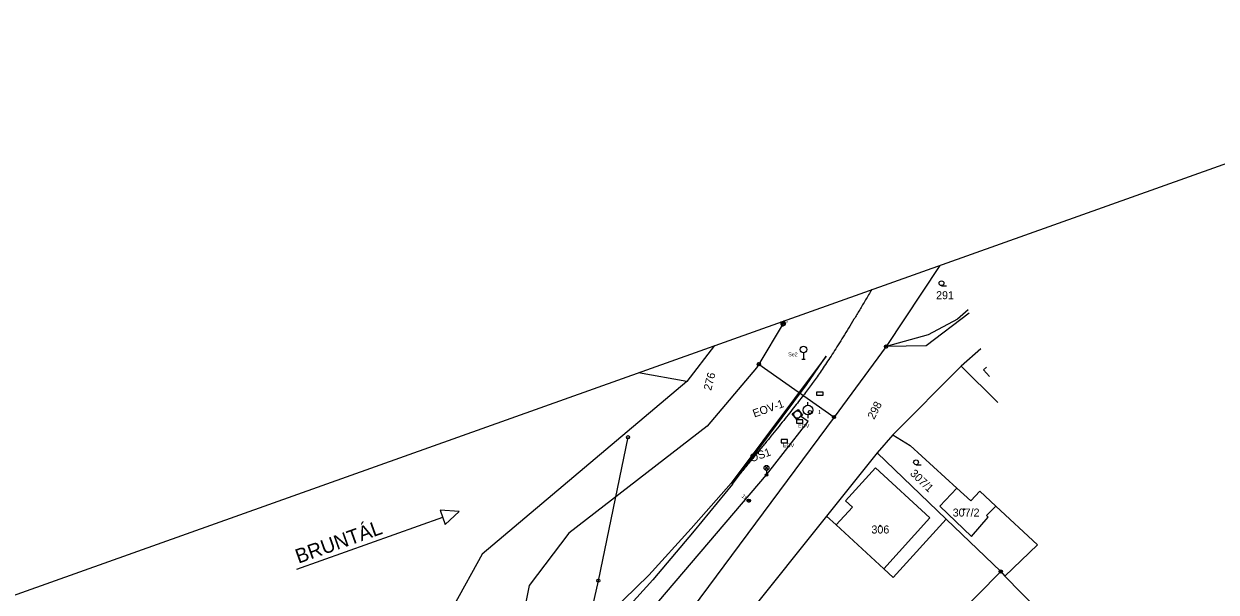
# Model space of a CAD drawing. Extents: x -734423 to 647242, y -1165906 to -111601.
# Drawn here: x -532656.7 to -532470.9, y -1114252 to -1114163.4 of the extents above; entities that cross this region are included whole.
import ezdxf

# ---------------------------------------------------------------- set-up
doc = ezdxf.new("R2010")
doc.units = 0
for name, color, linetype in [('Vrstva 1', 7, 'Continuous'), ('Vrstva 11', 7, 'Continuous'), ('Vrstva 13', 7, 'Continuous'), ('Vrstva 14', 7, 'Continuous'), ('Vrstva 15', 7, 'Continuous'), ('Vrstva 16', 7, 'Continuous'), ('Vrstva 17', 7, 'Continuous'), ('Vrstva 18', 7, 'Continuous'), ('Vrstva 19', 7, 'Continuous'), ('Vrstva 2', 7, 'Continuous'), ('Vrstva 24', 7, 'Continuous'), ('Vrstva 26', 7, 'Continuous'), ('Vrstva 4', 7, 'Continuous'), ('Vrstva 7', 7, 'Continuous'), ('Vrstva 8', 7, 'Continuous')]:
    doc.layers.add(name, color=color, linetype=linetype)

msp = doc.modelspace()

# ---------------------------------------------------------------- linework, layer by layer
at = {"layer": 'Vrstva 1'}
for p, q in [((-532588.86, -1114239.44), (-532591.83, -1114239.27)), ((-532591.83, -1114239.27), (-532591.03, -1114241.51)), ((-532591.03, -1114241.51), (-532588.86, -1114239.44)), ((-532614.17, -1114248.47), (-532591.44, -1114240.36))]:
    msp.add_line(p, q, dxfattribs=at)
at = {"layer": 'Vrstva 13'}
for p, q in [((-532509.35, -1114208.55), (-532516.07, -1114213.62)), ((-532516.07, -1114213.62), (-532522.32, -1114213.73)), ((-532528.66, -1114237.77), (-532523.97, -1114232.66)), ((-532523.97, -1114232.66), (-532515.52, -1114240.46)), ((-532527.58, -1114238.77), (-532528.66, -1114237.77)), ((-532530.12, -1114241.56), (-532527.58, -1114238.77)), ((-532515.52, -1114240.46), (-532522.68, -1114248.4))]:
    msp.add_line(p, q, dxfattribs=at)
at = {"layer": 'Vrstva 14'}
for p, q in [((-532513.96, -1114201.07), (-532522.32, -1114213.73)), ((-532509.53, -1114208.01), (-532511.21, -1114209.45)), ((-532538.38, -1114210.13), (-532542.14, -1114216.46)), ((-532538.21, -1114209.72), (-532538.38, -1114210.13)), ((-532511.21, -1114209.45), (-532515.78, -1114211.89)), ((-532515.78, -1114211.89), (-532522.32, -1114213.73)), ((-532549.07, -1114213.59), (-532553.37, -1114219.18)), ((-532522.32, -1114213.73), (-532530.44, -1114224.72)), ((-532507.57, -1114214.11), (-532510.62, -1114216.81)), ((-532560.9, -1114217.85), (-532560.93, -1114217.82)), ((-532553.37, -1114219.18), (-532560.9, -1114217.85)), ((-532542.5, -1114217.06), (-532550.19, -1114226.17)), ((-532542.14, -1114216.46), (-532542.5, -1114217.06)), ((-532542.14, -1114216.46), (-532530.44, -1114224.72)), ((-532510.62, -1114216.81), (-532521.29, -1114227.49)), ((-532510.62, -1114216.81), (-532504.88, -1114222.48)), ((-532507.12, -1114217.37), (-532506.66, -1114216.95)), ((-532506.2, -1114218.38), (-532507.12, -1114217.37)), ((-532553.37, -1114219.18), (-532585.27, -1114246.09)), ((-532530.44, -1114224.72), (-532572.43, -1114281.44)), ((-532550.19, -1114226.17), (-532571.79, -1114242.85)), ((-532521.29, -1114227.49), (-532523.7, -1114230.3)), ((-532521.29, -1114227.49), (-532518.59, -1114229.18)), ((-532518.59, -1114229.18), (-532511.28, -1114235.8)), ((-532523.7, -1114230.3), (-532531.61, -1114240.18)), ((-532512.98, -1114240.64), (-532523.7, -1114230.3)), ((-532511.28, -1114235.8), (-532513.94, -1114238.65)), ((-532511.28, -1114235.8), (-532509.12, -1114237.78)), ((-532509.12, -1114237.78), (-532507.7, -1114236.29)), ((-532507.7, -1114236.29), (-532505.24, -1114238.64)), ((-532531.61, -1114240.18), (-532544.05, -1114255.71)), ((-532531.61, -1114240.18), (-532530.12, -1114241.56)), ((-532513.94, -1114238.65), (-532509, -1114243.34)), ((-532506.69, -1114240.1), (-532505.24, -1114238.64)), ((-532506.4, -1114240.36), (-532506.69, -1114240.1)), ((-532505.24, -1114238.64), (-532498.72, -1114244.68)), ((-532530.12, -1114241.56), (-532522.68, -1114248.4)), ((-532521.21, -1114249.73), (-532512.98, -1114240.64)), ((-532504.46, -1114248.83), (-532512.98, -1114240.64)), ((-532509, -1114243.34), (-532506.4, -1114240.36)), ((-532571.79, -1114242.85), (-532577.97, -1114250.99)), ((-532498.72, -1114244.68), (-532503.79, -1114249.53)), ((-532585.27, -1114246.09), (-532589.68, -1114254.1)), ((-532522.68, -1114248.4), (-532521.21, -1114249.73)), ((-532520.48, -1114265.02), (-532504.46, -1114248.83)), ((-532504.46, -1114248.83), (-532503.79, -1114249.53)), ((-532503.79, -1114249.53), (-532498.62, -1114254.82)), ((-532577.97, -1114250.99), (-532580.38, -1114262.9))]:
    msp.add_line(p, q, dxfattribs=at)
at = {"layer": 'Vrstva 15'}
for p, q in [((-532531.68, -1114215.22), (-532546.47, -1114235.05)), ((-532535.44, -1114215.69), (-532534.94, -1114215.69)), ((-532535.19, -1114214.69), (-532535.19, -1114215.69)), ((-532534.72, -1114219.68), (-532531.68, -1114215.22)), ((-532546.27, -1114235.22), (-532534.72, -1114219.68)), ((-532534.5, -1114222.89), (-532534.5, -1114222.39)), ((-532534.5, -1114224.39), (-532534.5, -1114224.89)), ((-532541.23, -1114232.9), (-532540.71, -1114232.37)), ((-532541.23, -1114232.37), (-532540.71, -1114232.9)), ((-532540.97, -1114233.01), (-532540.97, -1114233.56)), ((-532546.47, -1114235.05), (-532552.68, -1114242.09)), ((-532546.27, -1114235.22), (-532552.26, -1114242.49)), ((-532559.33, -1114249.4), (-532552.68, -1114242.09)), ((-532552.26, -1114242.49), (-532558.67, -1114250.13)), ((-532565.21, -1114255.16), (-532559.33, -1114249.4)), ((-532558.67, -1114250.13), (-532564.19, -1114256.18))]:
    msp.add_line(p, q, dxfattribs=at)
for points in [[(-532533.15, -1114221.33), (-532532.15, -1114221.33), (-532532.15, -1114220.83), (-532533.15, -1114220.83)], [(-532536.3, -1114225.68), (-532535.3, -1114225.68), (-532535.3, -1114225.18), (-532536.3, -1114225.18)], [(-532538.7, -1114228.73), (-532537.7, -1114228.73), (-532537.7, -1114228.23), (-532538.7, -1114228.23)]]:
    msp.add_lwpolyline(points, close=True, dxfattribs=at)
for centre, radius in [((-532535.19, -1114214.19), 0.5), ((-532534.5, -1114223.64), 0.75), ((-532534.2, -1114223.95), 0.25), ((-532562.56, -1114227.88), 0.25), ((-532540.97, -1114232.64), 0.375), ((-532540.97, -1114233.76), 0.2), ((-532567.18, -1114250.25), 0.25)]:
    msp.add_circle(centre, radius, dxfattribs=at)
msp.add_open_spline([(-532524.57, -1114204.85), (-532530.44, -1114214.87), (-532537.33, -1114224.26), (-532544.98, -1114233.43)], degree=2, dxfattribs=at)
at = {"layer": 'Vrstva 16'}
for p, q in [((-532522.32, -1114213.73), (-532522.32, -1114213.73)), ((-532542.14, -1114216.46), (-532542.14, -1114216.46)), ((-532530.44, -1114224.72), (-532530.44, -1114224.72)), ((-532504.46, -1114248.83), (-532504.46, -1114248.83))]:
    msp.add_line(p, q, dxfattribs=at)
for centre, radius in [((-532522.32, -1114213.73), 0.258), ((-532522.32, -1114213.73), 0.25), ((-532522.32, -1114213.73), 0.05), ((-532522.32, -1114213.73), 0.05), ((-532542.14, -1114216.46), 0.258), ((-532542.14, -1114216.46), 0.25), ((-532542.14, -1114216.46), 0.05), ((-532542.14, -1114216.46), 0.05), ((-532530.44, -1114224.72), 0.258), ((-532530.44, -1114224.72), 0.25), ((-532530.44, -1114224.72), 0.05), ((-532530.44, -1114224.72), 0.05), ((-532504.46, -1114248.83), 0.258), ((-532504.46, -1114248.83), 0.25), ((-532504.46, -1114248.83), 0.05), ((-532504.46, -1114248.83), 0.05)]:
    msp.add_circle(centre, radius, dxfattribs=at)
at = {"layer": 'Vrstva 17'}
msp.add_circle((-532538.38, -1114210.12), 0.0164, dxfattribs=at)
msp.add_arc((-532538.38, -1114210.12), 0.375, 140.0548, 79.193, dxfattribs=at)
at = {"layer": 'Vrstva 18'}
for radius in [0.188, 0.00025]:
    msp.add_circle((-532538.38, -1114210.12), radius, dxfattribs=at)
at = {"layer": 'Vrstva 19'}
for p, q in [((-532513.68, -1114204.24), (-532512.88, -1114204.24)), ((-532517.65, -1114232.16), (-532516.85, -1114232.16))]:
    msp.add_line(p, q, dxfattribs=at)
for centre, radius in [((-532513.68, -1114203.86), 0.375), ((-532517.65, -1114231.78), 0.375), ((-532510.17, -1114239.11), 0.0875), ((-532523.25, -1114241.69), 0.0875)]:
    msp.add_circle(centre, radius, dxfattribs=at)
at = {"layer": 'Vrstva 2'}
msp.add_lwpolyline([(-532846.62, -1114416.18), (-532848.11, -1114412.13), (-532808.84, -1114398.2), (-532780.05, -1114388.6), (-532754.69, -1114379.36), (-532726.64, -1114369.2), (-532698.29, -1114356.28), (-532677.56, -1114346.43), (-532659.12, -1114337.79), (-532635.25, -1114325.58), (-532614.01, -1114308.56), (-532586.09, -1114284.59), (-532565.53, -1114262.57), (-532540.97, -1114233.76), (-532534.45, -1114225.44), (-532535.66, -1114224.61)], dxfattribs=at)
at = {"layer": 'Vrstva 24'}
msp.add_lwpolyline([(-532562.56, -1114227.88), (-532567.18, -1114250.25), (-532573.56, -1114278.28), (-532581.66, -1114307.38), (-532563.97, -1114281.96)], dxfattribs=at)
at = {"layer": 'Vrstva 26'}
for radius in [0.25, 0.05]:
    msp.add_circle((-532543.71, -1114237.76), radius, dxfattribs=at)
at = {"layer": 'Vrstva 4'}
msp.add_line((-533100.62, -1114410.25), (-532408.31, -1114163.4), dxfattribs=at)
at = {"layer": 'Vrstva 7'}
for p, q in [((-532536.94, -1114224.23), (-532536.05, -1114223.53)), ((-532536.05, -1114223.53), (-532535.35, -1114224.42)), ((-532536.24, -1114225.12), (-532536.94, -1114224.23)), ((-532535.35, -1114224.42), (-532536.24, -1114225.12))]:
    msp.add_line(p, q, dxfattribs=at)
msp.add_circle((-532536.15, -1114224.32), 0.563, dxfattribs=at)

# ---------------------------------------------------------------- texts
at = {"layer": 'Vrstva 1'}
msp.add_text('BRUNTÁL', height=2.257, rotation=19.6237, dxfattribs=at).set_placement((-532613.92, -1114247.61))
at = {"layer": 'Vrstva 11'}
for s, rotation, p in [('291', 359.9996, (-532514.53, -1114206.35)), ('276', 75.5726, (-532549.59, -1114220.66)), ('298', 63.0248, (-532524.19, -1114225.19)), ('307/1', 315.8712, (-532518.67, -1114233.64)), ('307/2', 359.9996, (-532511.94, -1114240.25)), ('306', 359.9996, (-532524.61, -1114242.89))]:
    msp.add_text(s, height=1.25, rotation=rotation, dxfattribs=at).set_placement(p)
at = {"layer": 'Vrstva 18'}
msp.add_text(' 617', height=0.3, dxfattribs=at).set_placement((-532538.38, -1114210.12))
at = {"layer": 'Vrstva 26'}
for s, p in [('Se2', (-532537.58, -1114215.25)), ('1', (-532532.93, -1114224.25)), ('EOV', (-532536.03, -1114226.39)), ('EOV', (-532538.39, -1114229.43))]:
    msp.add_text(s, height=0.6, dxfattribs=at).set_placement(p)
msp.add_text('19,8', height=0.6, rotation=320.5152, dxfattribs=at).set_placement((-532544.91, -1114237.16))
at = {"layer": 'Vrstva 8'}
for s, p in [('EOV-1', (-532542.85, -1114224.81)), ('OS1', (-532543.31, -1114231.79))]:
    msp.add_text(s, height=1.248, rotation=19.5946, dxfattribs=at).set_placement(p)

doc.saveas('drawing.dxf')
